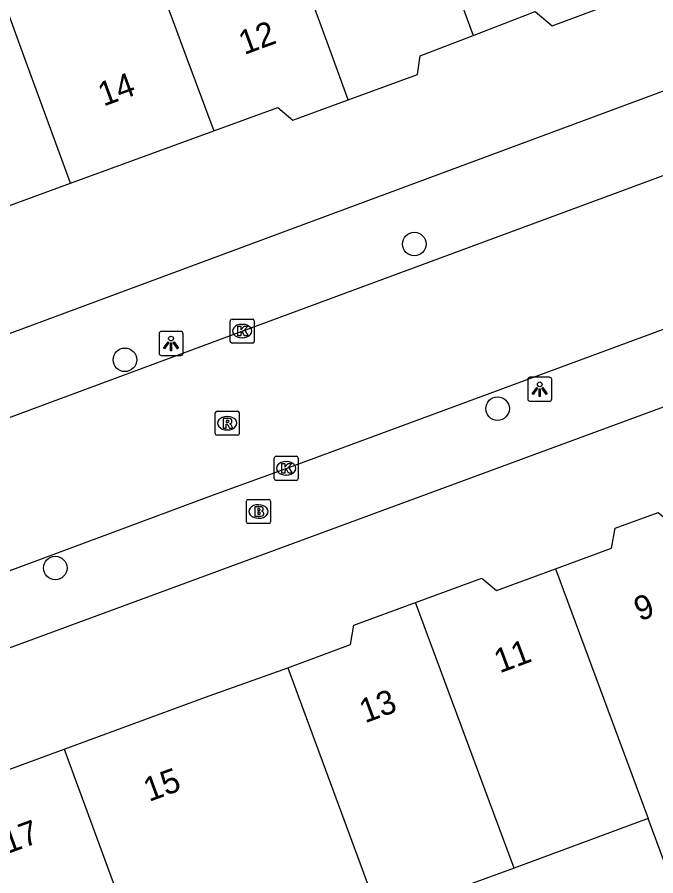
# Model space of a CAD drawing. Extents: x 161258 to 161838, y 380836 to 381727.
# Drawn here: x 161661.92 to 161688.43, y 381465.96 to 381501.61 of the extents above; entities that cross this region are included whole.
import ezdxf

# ---------------------------------------------------------------- set-up
doc = ezdxf.new("R2010")
doc.units = 0
for name, color, linetype in [('IMGEO_Boom', 7, 'Continuous'), ('IMGEO_Brandkraan', 7, 'Continuous'), ('IMGEO_Kolk', 7, 'Continuous'), ('IMGEO_Lichtpunt', 7, 'Continuous'), ('IMGEO_Pand', 7, 'Continuous'), ('IMGEO_Pand_nummerreeks', 7, 'Continuous'), ('IMGEO_Rijbaan_lokaal_open', 7, 'Continuous'), ('IMGEO_Rioolput', 7, 'Continuous'), ('IMGEO_Voetpad_open', 7, 'Continuous')]:
    doc.layers.add(name, color=color, linetype=linetype)

msp = doc.modelspace()

# ---------------------------------------------------------------- linework, layer by layer
at = {"layer": 'IMGEO_Boom'}
for centre in [(161678.404, 381492.188), (161666.395, 381487.382), (161681.859, 381485.354), (161663.506, 381478.737)]:
    msp.add_circle(centre, 0.489, dxfattribs=at)
at = {"layer": 'IMGEO_Brandkraan'}
for p, q in [((161671.437, 381480.657), (161671.437, 381481.509)), ((161671.512, 381481.583), (161672.364, 381481.583)), ((161672.438, 381481.509), (161672.438, 381480.657)), ((161671.925, 381481.363), (161671.95, 381481.363)), ((161671.948, 381480.803), (161671.923, 381480.803)), ((161672.364, 381480.583), (161671.512, 381480.583))]:
    msp.add_line(p, q, dxfattribs=at)
for points in [[(161671.437, 381480.657), (161671.437, 381481.509)], [(161671.512, 381481.583), (161672.364, 381481.583)], [(161672.438, 381481.509), (161672.438, 381480.657)], [(161671.785, 381481.283), (161671.785, 381480.883), (161671.998, 381480.883)], [(161672.016, 381481.283), (161671.785, 381481.283)], [(161671.964, 381481.202), (161671.91, 381481.202), (161671.91, 381481.126)], [(161671.91, 381481.126), (161671.963, 381481.126)], [(161671.972, 381481.05), (161671.91, 381481.05), (161671.91, 381480.969)], [(161671.91, 381480.969), (161671.972, 381480.969)], [(161672.364, 381480.583), (161671.512, 381480.583)]]:
    msp.add_lwpolyline(points, dxfattribs=at)
for centre, radius, start, end in [((161671.514, 381481.507), 0.0765, 91.552, 178.448), ((161671.514, 381481.507), 0.0765, 91.552, 178.448), ((161672.362, 381481.507), 0.0765, 1.552, 88.448), ((161672.362, 381481.507), 0.0765, 1.552, 88.448), ((161671.965, 381481.164), 0.0379, 267.8285, 90.9355), ((161671.973, 381481.009), 0.0404, 269.8759, 90.5077), ((161672.02, 381481.138), 0.145, 59.4692, 91.5367), ((161672.045, 381481.185), 0.0922, 285.5137, 58.1501), ((161672.05, 381480.993), 0.105, 301.3115, 78.989), ((161672.004, 381481.134), 0.251, 268.6676, 293.5347), ((161671.514, 381480.659), 0.0765, 181.552, 268.448), ((161671.514, 381480.659), 0.0765, 181.552, 268.448), ((161672.362, 381480.659), 0.0765, 271.552, 358.448), ((161672.362, 381480.659), 0.0765, 271.552, 358.448)]:
    msp.add_arc(centre, radius, start, end, dxfattribs=at)
for centre, major_axis, ratio, start_param, end_param in [((161671.924, 381481.083), (-0.387, 0.002), 0.722429, 4.712389, 7.853982), ((161671.949, 381481.083), (-0.39, 0.002), 0.717154, 1.570796, 4.712389)]:
    msp.add_ellipse(centre, major_axis=major_axis, ratio=ratio, start_param=start_param, end_param=end_param, dxfattribs=at)
at = {"layer": 'IMGEO_Kolk'}
for p, q in [((161670.764, 381488.146), (161670.764, 381488.998)), ((161670.839, 381489.072), (161671.691, 381489.072)), ((161671.765, 381488.998), (161671.765, 381488.146)), ((161671.252, 381488.852), (161671.277, 381488.852)), ((161671.275, 381488.292), (161671.25, 381488.292)), ((161671.691, 381488.072), (161670.839, 381488.072)), ((161672.59, 381482.449), (161672.59, 381483.301)), ((161672.665, 381483.375), (161673.517, 381483.375)), ((161673.591, 381483.301), (161673.591, 381482.449)), ((161673.078, 381483.155), (161673.103, 381483.155)), ((161673.101, 381482.595), (161673.076, 381482.595)), ((161673.517, 381482.375), (161672.665, 381482.375))]:
    msp.add_line(p, q, dxfattribs=at)
for points in [[(161670.764, 381488.146), (161670.764, 381488.998)], [(161670.839, 381489.072), (161671.691, 381489.072)], [(161671.765, 381488.998), (161671.765, 381488.146)], [(161671.085, 381488.772), (161671.208, 381488.772), (161671.208, 381488.621), (161671.338, 381488.772), (161671.502, 381488.772), (161671.356, 381488.621), (161671.509, 381488.372), (161671.357, 381488.372), (161671.272, 381488.536), (161671.208, 381488.469), (161671.208, 381488.372), (161671.085, 381488.372), (161671.085, 381488.772)], [(161671.691, 381488.072), (161670.839, 381488.072)], [(161672.59, 381482.449), (161672.59, 381483.301)], [(161672.665, 381483.375), (161673.517, 381483.375)], [(161673.591, 381483.301), (161673.591, 381482.449)], [(161672.911, 381483.075), (161673.034, 381483.075), (161673.034, 381482.924), (161673.164, 381483.075), (161673.328, 381483.075), (161673.182, 381482.924), (161673.335, 381482.675), (161673.183, 381482.675), (161673.098, 381482.839), (161673.034, 381482.772), (161673.034, 381482.675), (161672.911, 381482.675), (161672.911, 381483.075)], [(161673.517, 381482.375), (161672.665, 381482.375)]]:
    msp.add_lwpolyline(points, dxfattribs=at)
for centre, start, end in [((161670.841, 381488.996), 91.552, 178.448), ((161670.841, 381488.996), 91.552, 178.448), ((161671.689, 381488.996), 1.552, 88.448), ((161671.689, 381488.996), 1.552, 88.448), ((161670.841, 381488.148), 181.552, 268.448), ((161670.841, 381488.148), 181.552, 268.448), ((161671.689, 381488.148), 271.552, 358.448), ((161671.689, 381488.148), 271.552, 358.448), ((161672.667, 381483.299), 91.552, 178.448), ((161672.667, 381483.299), 91.552, 178.448), ((161673.515, 381483.299), 1.552, 88.448), ((161673.515, 381483.299), 1.552, 88.448), ((161672.667, 381482.451), 181.552, 268.448), ((161672.667, 381482.451), 181.552, 268.448), ((161673.515, 381482.451), 271.552, 358.448), ((161673.515, 381482.451), 271.552, 358.448)]:
    msp.add_arc(centre, 0.0765, start, end, dxfattribs=at)
for centre, major_axis, ratio, start_param, end_param in [((161671.251, 381488.572), (-0.387, 0.002), 0.722429, 4.712389, 7.853982), ((161671.276, 381488.572), (-0.39, 0.002), 0.717154, 1.570796, 4.712389), ((161673.077, 381482.875), (-0.387, 0.002), 0.722429, 4.712389, 7.853982), ((161673.102, 381482.875), (-0.39, 0.002), 0.717154, 1.570796, 4.712389)]:
    msp.add_ellipse(centre, major_axis=major_axis, ratio=ratio, start_param=start_param, end_param=end_param, dxfattribs=at)
at = {"layer": 'IMGEO_Lichtpunt'}
for p, q in [((161668.713, 381488.561), (161667.905, 381488.561)), ((161668.713, 381488.561), (161667.905, 381488.561)), ((161667.811, 381488.466), (161667.811, 381487.659)), ((161667.811, 381488.466), (161667.811, 381487.659)), ((161668.807, 381487.659), (161668.807, 381488.466)), ((161668.807, 381487.659), (161668.807, 381488.466)), ((161667.905, 381487.565), (161668.713, 381487.565)), ((161667.905, 381487.565), (161668.713, 381487.565)), ((161683.11, 381486.564), (161683.11, 381485.757)), ((161683.11, 381486.564), (161683.11, 381485.757)), ((161684.012, 381486.659), (161683.204, 381486.659)), ((161684.012, 381486.659), (161683.204, 381486.659)), ((161684.106, 381485.757), (161684.106, 381486.564)), ((161684.106, 381485.757), (161684.106, 381486.564)), ((161683.204, 381485.663), (161684.012, 381485.663)), ((161683.204, 381485.663), (161684.012, 381485.663))]:
    msp.add_line(p, q, dxfattribs=at)
for points in [[(161668.185, 381488.13), (161668.224, 381488.102), (161668.036, 381487.84), (161667.998, 381487.867), (161668.185, 381488.13)], [(161668.287, 381488.082), (161668.334, 381488.082), (161668.334, 381487.76), (161668.287, 381487.76), (161668.287, 381488.082)], [(161668.397, 381488.102), (161668.435, 381488.129), (161668.622, 381487.867), (161668.583, 381487.839), (161668.397, 381488.102)], [(161683.484, 381486.228), (161683.523, 381486.2), (161683.335, 381485.938), (161683.297, 381485.965), (161683.484, 381486.228)], [(161683.586, 381486.18), (161683.633, 381486.18), (161683.633, 381485.858), (161683.586, 381485.858), (161683.586, 381486.18)], [(161683.696, 381486.2), (161683.734, 381486.227), (161683.921, 381485.965), (161683.882, 381485.937), (161683.696, 381486.2)]]:
    msp.add_lwpolyline(points, dxfattribs=at)
for centre in [(161668.31, 381488.264), (161683.609, 381486.362)]:
    msp.add_circle(centre, 0.0994, dxfattribs=at)
for centre, start, end in [((161667.905, 381488.466), 90, 180), ((161667.905, 381488.466), 90, 180), ((161668.713, 381488.466), 0, 90), ((161668.713, 381488.466), 0, 90), ((161667.905, 381487.659), 180, 270), ((161667.905, 381487.659), 180, 270), ((161668.713, 381487.659), 270, 0), ((161668.713, 381487.659), 270, 360), ((161683.204, 381486.564), 90, 180), ((161683.204, 381486.564), 90, 180), ((161684.012, 381486.564), 0, 90), ((161684.012, 381486.564), 0, 90), ((161683.204, 381485.757), 180, 270), ((161683.204, 381485.757), 180, 270), ((161684.012, 381485.757), 270, 0), ((161684.012, 381485.757), 270, 360)]:
    msp.add_arc(centre, 0.0946, start, end, dxfattribs=at)
at = {"layer": 'IMGEO_Pand'}
for points in [[(161675.66, 381498.173), (161674.992, 381500), (161671.22, 381510.325)], [(161677.836, 381509.087), (161680.846, 381500.847)], [(161666.051, 381507.805), (161668.918, 381500), (161670.084, 381496.883)], [(161664.137, 381494.711), (161662.204, 381500), (161660.262, 381505.316)], [(161680.846, 381500.847), (161683.416, 381501.839), (161684.123, 381501.254), (161686.389, 381502.096)], [(161675.66, 381498.173), (161678.535, 381499.223), (161678.65, 381500), (161680.846, 381500.847)], [(161670.084, 381496.883), (161672.736, 381497.852), (161673.357, 381497.332), (161675.66, 381498.173)], [(161664.137, 381494.711), (161670.084, 381496.883)], [(161657.945, 381492.45), (161664.137, 381494.711)], [(161684.26, 381478.705), (161686.591, 381479.563), (161686.733, 381480.387), (161688.528, 381481.047), (161689.146, 381480.532), (161689.611, 381480.703), (161691.302, 381476.105), (161692.439, 381476.523), (161693.593, 381476.342), (161694.477, 381475.59), (161694.867, 381474.529), (161694.694, 381473.362), (161693.927, 381472.48), (161692.787, 381472.069), (161689.671, 381470.923), (161690.993, 381467.328), (161688.783, 381466.515), (161688.108, 381468.334)], [(161678.452, 381477.305), (161681.205, 381478.318), (161681.818, 381477.807), (161684.26, 381478.705)], [(161684.26, 381478.705), (161688.108, 381468.334)], [(161673.154, 381474.595), (161675.759, 381475.554), (161675.899, 381476.366), (161678.452, 381477.305)], [(161682.544, 381466.28), (161681.703, 381468.546), (161678.452, 381477.305)], [(161663.871, 381471.218), (161669.893, 381473.433), (161673.154, 381474.595)], [(161673.154, 381474.595), (161676.142, 381466.5), (161677.653, 381462.391)], [(161658.144, 381469.111), (161663.871, 381471.218)], [(161663.871, 381471.218), (161666.657, 381463.642)], [(161688.108, 381468.334), (161682.544, 381466.28)], [(161682.544, 381466.28), (161679.175, 381465.037), (161679.612, 381464.021), (161679.11, 381462.928), (161677.653, 381462.391)]]:
    msp.add_lwpolyline(points, dxfattribs=at)
at = {"layer": 'IMGEO_Rijbaan_lokaal_open'}
for points in [[(161658.225, 381483.74), (161671.265, 381488.572), (161693.452, 381496.782), (161725.523, 381508.66)], [(161660.386, 381478.179), (161666.398, 381480.402), (161670.065, 381481.78), (161673.091, 381482.875), (161690.547, 381489.321), (161692.364, 381489.984)]]:
    msp.add_lwpolyline(points, dxfattribs=at)
at = {"layer": 'IMGEO_Rioolput'}
for p, q in [((161670.142, 381484.323), (161670.142, 381485.175)), ((161670.217, 381485.249), (161671.069, 381485.249)), ((161670.63, 381485.029), (161670.655, 381485.029)), ((161671.143, 381485.175), (161671.143, 381484.323)), ((161671.069, 381484.249), (161670.217, 381484.249)), ((161670.653, 381484.469), (161670.628, 381484.469))]:
    msp.add_line(p, q, dxfattribs=at)
for points in [[(161670.142, 381484.323), (161670.142, 381485.175)], [(161670.217, 381485.249), (161671.069, 381485.249)], [(161671.143, 381485.175), (161671.143, 381484.323)], [(161670.731, 381484.947), (161670.479, 381484.949), (161670.479, 381484.549)], [(161670.479, 381484.549), (161670.603, 381484.549), (161670.603, 381484.711), (161670.614, 381484.711)], [(161670.657, 381484.868), (161670.603, 381484.868), (161670.603, 381484.787)], [(161670.603, 381484.787), (161670.655, 381484.787)], [(161670.661, 381484.682), (161670.732, 381484.549), (161670.872, 381484.549), (161670.807, 381484.675)], [(161671.069, 381484.249), (161670.217, 381484.249)]]:
    msp.add_lwpolyline(points, dxfattribs=at)
for centre, radius, start, end in [((161670.219, 381485.173), 0.0765, 91.552, 178.448), ((161670.219, 381485.173), 0.0765, 91.552, 178.448), ((161671.067, 381485.173), 0.0765, 1.552, 88.448), ((161671.067, 381485.173), 0.0765, 1.552, 88.448), ((161670.613, 381484.658), 0.0533, 26.0293, 88.6989), ((161670.639, 381484.976), 0.19, 274.7715, 282.9687), ((161670.663, 381484.772), 0.0964, 77.0061, 93.1865), ((161670.677, 381484.829), 0.0378, 276.6634, 79.6772), ((161670.73, 381484.837), 0.109, 350.3612, 89.416), ((161670.728, 381484.837), 0.112, 277.5842, 350.9817), ((161670.712, 381484.622), 0.108, 29.5134, 73.7905), ((161670.219, 381484.325), 0.0765, 181.552, 268.448), ((161670.219, 381484.325), 0.0765, 181.552, 268.448), ((161671.067, 381484.325), 0.0765, 271.552, 358.448), ((161671.067, 381484.325), 0.0765, 271.552, 358.448)]:
    msp.add_arc(centre, radius, start, end, dxfattribs=at)
for centre, major_axis, ratio, start_param, end_param in [((161670.629, 381484.749), (-0.387, 0.002), 0.722429, 4.712389, 7.853982), ((161670.654, 381484.749), (-0.39, 0.002), 0.717154, 1.570796, 4.712389)]:
    msp.add_ellipse(centre, major_axis=major_axis, ratio=ratio, start_param=start_param, end_param=end_param, dxfattribs=at)
at = {"layer": 'IMGEO_Voetpad_open'}
for points in [[(161704.512, 381504.387), (161692.684, 381500), (161641.589, 381481.048)], [(161692.567, 381486.83), (161622.485, 381460.994)]]:
    msp.add_lwpolyline(points, dxfattribs=at)

# ---------------------------------------------------------------- texts
at = {"layer": 'IMGEO_Pand_nummerreeks'}
for s, rotation, p in [('12', 20.2099, (161671.346, 381500.034)), ('14', 20.065, (161665.505, 381497.893)), ('9', 20.3629, (161687.753, 381476.515)), ('11', 20.3629, (161681.946, 381474.359)), ('13', 20.3629, (161676.357, 381472.284)), ('15', 20.1977, (161667.395, 381469.02)), ('17', 20.1977, (161661.514, 381466.856))]:
    msp.add_text(s, height=1, rotation=rotation, dxfattribs=at).set_placement(p)

doc.saveas('drawing.dxf')
